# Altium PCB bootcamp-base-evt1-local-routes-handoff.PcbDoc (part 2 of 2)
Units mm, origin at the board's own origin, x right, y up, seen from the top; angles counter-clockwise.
Board outline 49.31 x 77.41 mm, 4 copper layers (Top Layer, Internal Plane 1, Internal Plane 2, Bottom Layer), stack 1.597 mm thick; 167 components, 119 nets, 1376 pads, 238 vias.
Unrouted connection lines stored in the file: 50.
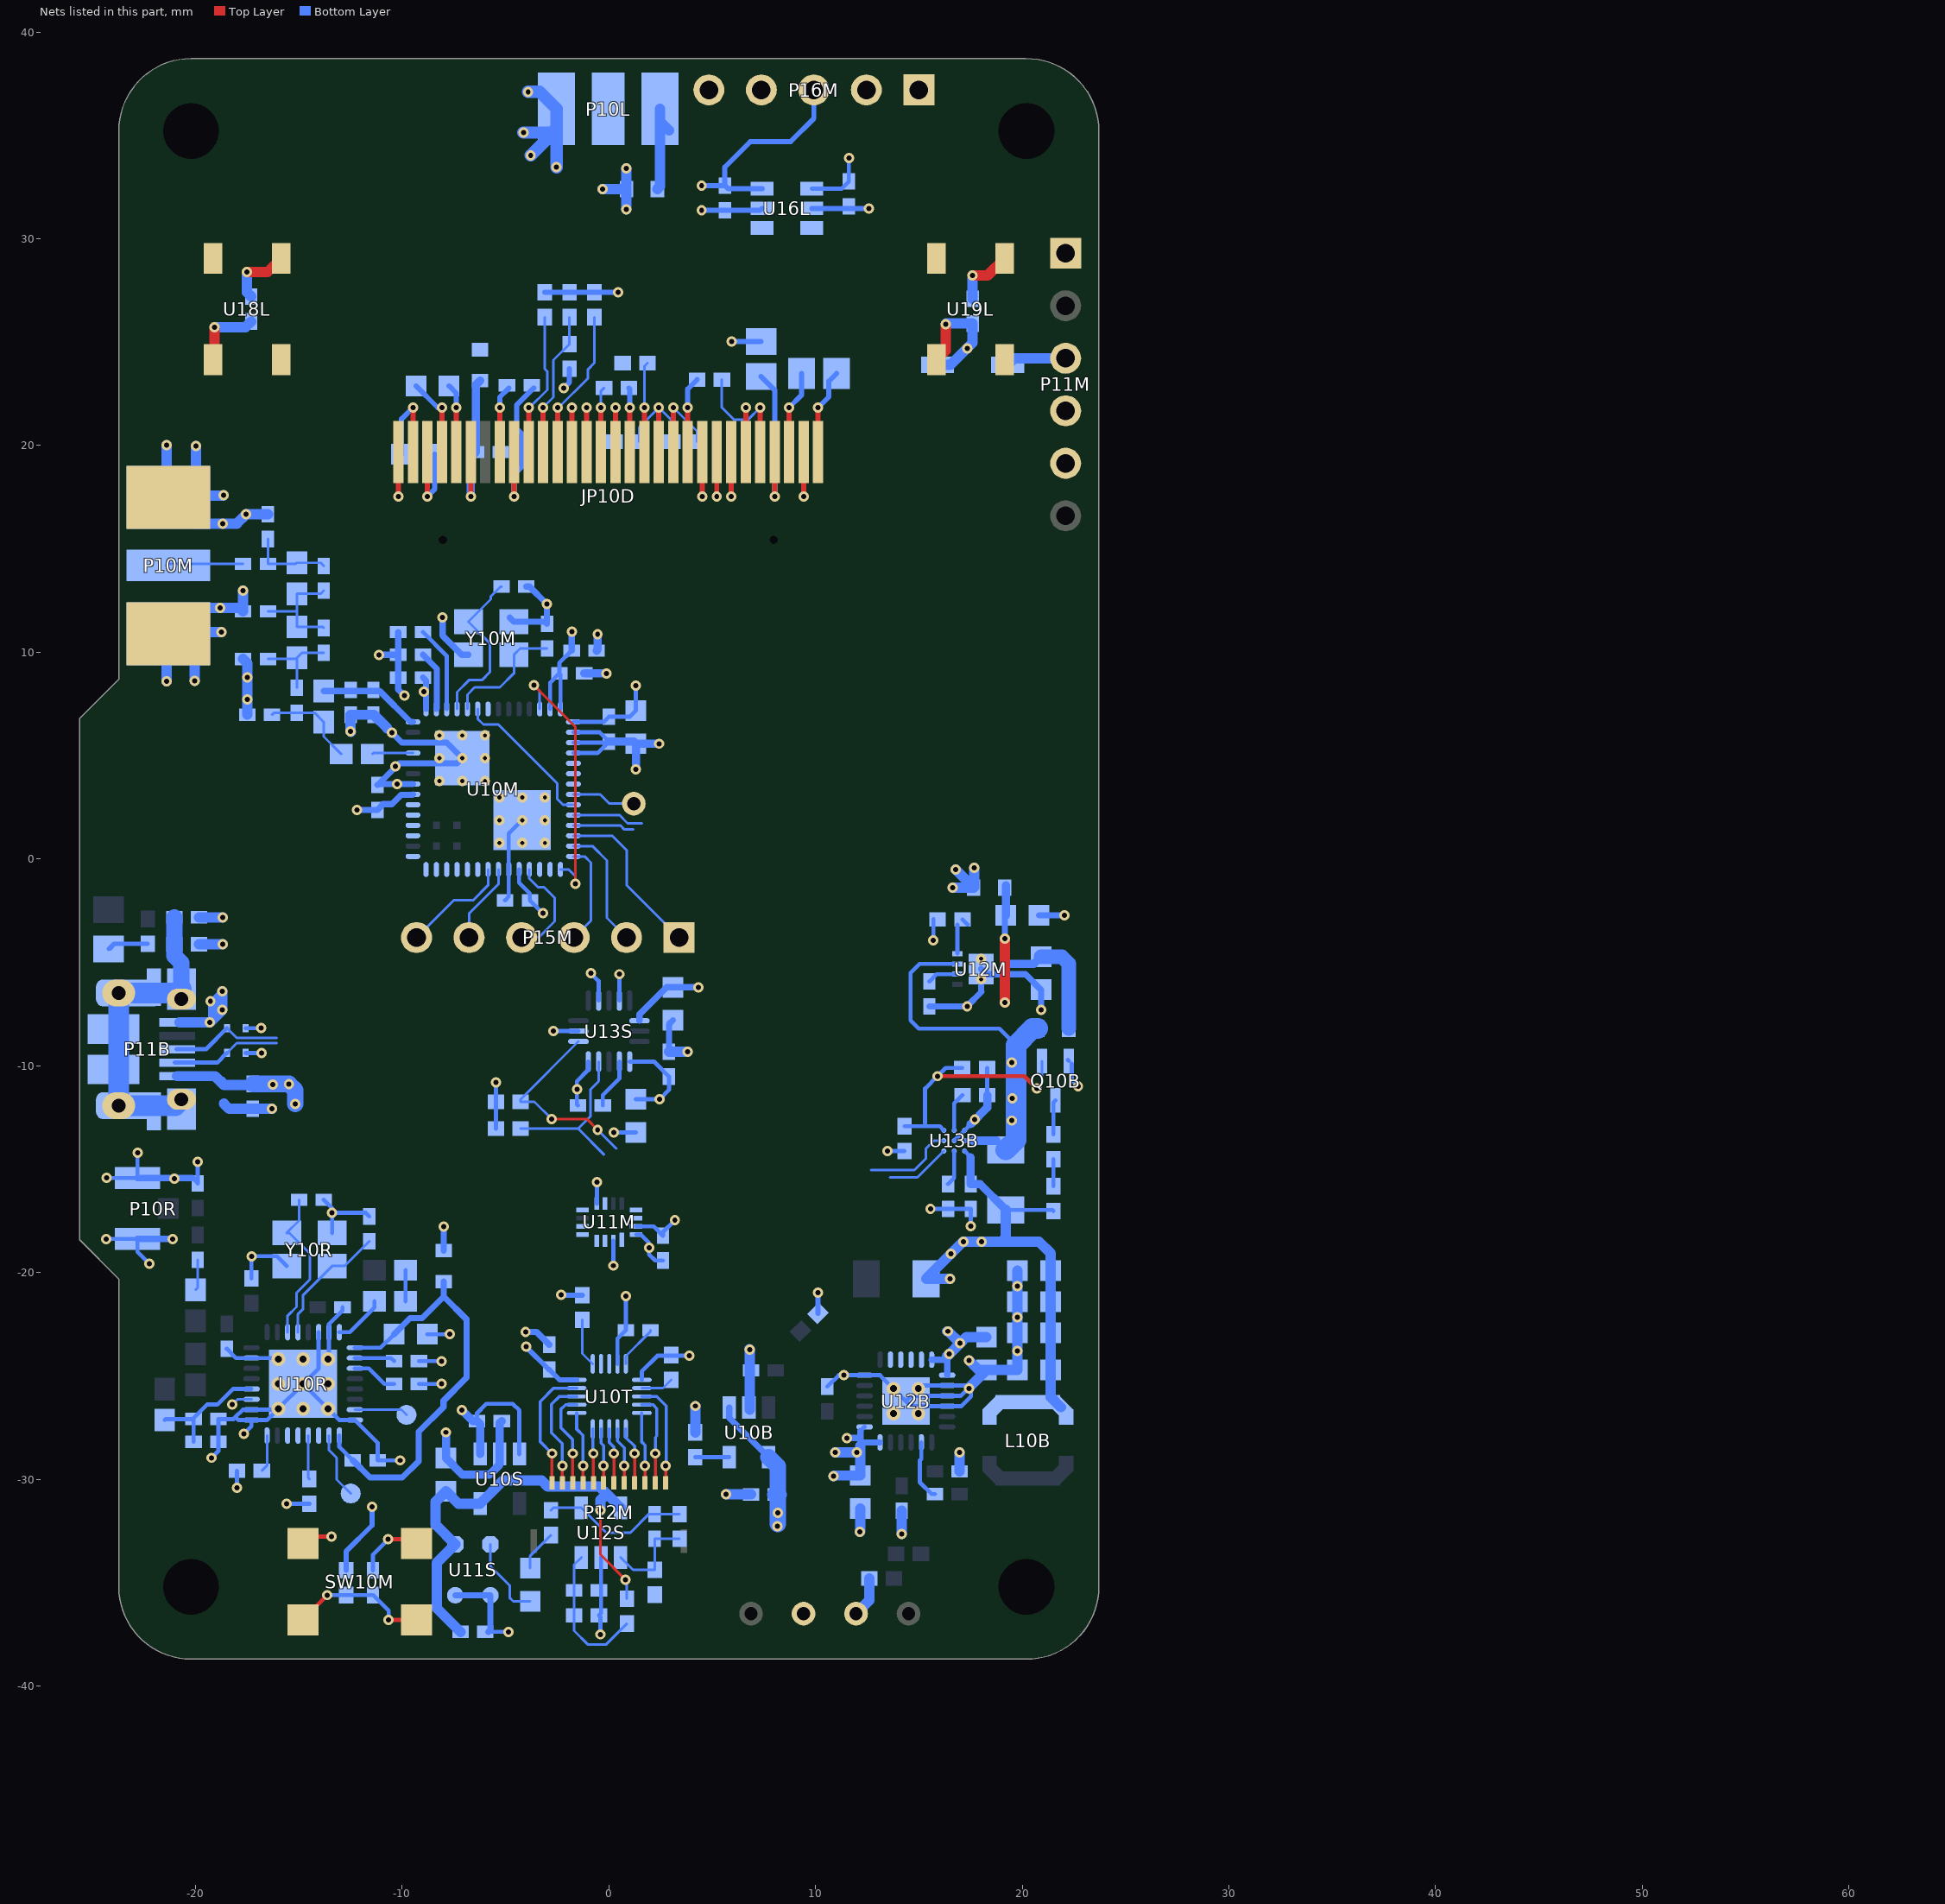
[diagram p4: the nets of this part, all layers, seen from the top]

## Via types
v1: diameter 0.5, hole 0.25, Top Layer to Bottom Layer, tented both sides, 205 vias
v2: diameter 0.5, hole 0.2, Top Layer to Bottom Layer, 18 vias
v3: diameter 0.66, hole 0.33, Top Layer to Bottom Layer, tented top, 13 vias
v4: diameter 0.5, hole 0.2, Top Layer to Bottom Layer, tented top, 2 vias

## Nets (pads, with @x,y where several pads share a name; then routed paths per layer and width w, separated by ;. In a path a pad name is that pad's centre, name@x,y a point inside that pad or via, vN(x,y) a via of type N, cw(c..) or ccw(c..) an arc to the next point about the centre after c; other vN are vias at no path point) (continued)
BLE_RDYN: R11R.1 U10M.26 U10R.16 | length 1.8
  Bottom Layer w0.125: R11R.1@-16.786,-29.584 -16.536,-29.334 U10R.16@-16.536,-27.884
BLE_REQN: R12R.1 U10M.7 U10R.12 | length 2.1
  Bottom Layer w0.125: U10R.12@-14.536,-27.884 -14.536,-29.934 R12R.1@-14.486,-29.984
BLE_RST: U10R.19 U11M.5 | length 1
  Bottom Layer w0.125: v1(-18.211,-26.384) -17.961,-26.134 U10R.19@-17.286,-26.134
BLE_VDDPA: C19R.2 C20R.2 L14R.2 U10R.20 | length 6
  Bottom Layer w0.2: L14R.2@-21.486,-27.134 -21.436,-27.084 C19R.2@-20.086,-27.084 ; C20R.2@-20.086,-28.184 C19R.2@-20.086,-27.084 ; U10R.20@-17.286,-25.634 -18.186,-25.634 -18.936,-26.384 -19.436,-26.384 -20.086,-27.034 C19R.2@-20.086,-27.084
BLE_XC1: C10R.1 U10R.28 Y10R.2 | length 6.2
  Bottom Layer w0.125: U10R.28@-15.036,-22.884 -15.036,-22.009 -14.786,-21.759 -14.786,-21.084 Y10R.2@-13.386,-19.684 -12.786,-19.684 C10R.1@-11.586,-18.484
BLE_XC2: C11R.1 U10R.27 Y10R.1 | length 7.6
  Bottom Layer w0.125: U10R.27@-15.536,-22.884 -15.536,-22.084 -15.111,-21.659 -15.111,-20.984 -14.461,-20.334 -14.461,-19.084 -15.461,-18.084 Y10R.1@-15.586,-18.084 -14.986,-17.484 C11R.1@-14.986,-16.484
BS0: JP10D.10 R11D.2 | length 7
  Top Layer w0.25: JP10D.10@-3.878,19.684 v1(-3.878,21.834)
  Bottom Layer w0.125: v1(-3.878,21.834) -3.838,21.834 -2.978,22.694 -2.978,23.584 -3.103,23.709 R11D.2@-3.103,26.209
BS1: JP10D.11 R15D.2 R16D.2 | length 7.1
  Top Layer w0.25: JP10D.11@-3.178,19.684 v1(-3.178,21.834)
  Bottom Layer w0.125: v1(-3.178,21.834) -2.678,22.334 -2.678,24.134 R16D.2@-1.903,24.909 R15D.2@-1.903,26.209
BS2: JP10D.12 R17D.2 | length 7.3
  Top Layer w0.25: JP10D.12@-2.478,19.684 v1(-2.478,21.834)
  Bottom Layer w0.125: v1(-2.478,21.834) -2.428,21.834 -1.003,23.259 -1.003,23.684 -0.703,23.984 R17D.2@-0.703,26.209
DAC0_OUT: J17M.1 U10M.8 | length 3.1
  Bottom Layer w0.125: U10M.8@-1.712,3.129 -0.417,3.129 0.033,2.679 J17M.1@1.208,2.679
DUART_RX: P11M.4 U10M.29
DUART_TX: P11M.5 U10M.31
GG_INT: Q10B.1 R22B.1 R28B.2 U11M.8 U13B.A1 | length 12.5
  Top Layer w0.2: v1(15.9,-10.5) 20.1,-10.5 v1(20.7,-11.1)
  Bottom Layer w0.125: v1(20.7,-11.1) 20.958,-10.842 Q10B.1@20.958,-9.771
  Bottom Layer w0.2: R22B.1@14.308,-12.921 15.3,-12.921 ; U13B.A1@16.208,-13.121 16.008,-12.921 15.3,-12.921 ; R28B.2@17.1,-10.1 16.3,-10.1 v1(15.9,-10.5) 15.3,-11.1 15.3,-12.921
GG_VDD: C26B.1 U13B.B3 | length 1.7
  Bottom Layer w0.2: C26B.1@16.408,-15.721 16.708,-15.421 U13B.B3@16.708,-14.121
GND: C10B.2 C10L.2 C10M.2 C10R.2 C10S.2 C10T.2 C11B.2 C11L.2 C11M.2 C11R.2 C11S.2 C11T.2 C12D.2 C12L.2 C12M.2 C12R.2 C13D.2 C13L.2 C13M.2 C13R.2 C14D.2 C14M.2 C14S.2 C15B.2 C15D.2 C15M.2 C15R.1 C15S.2 C16B.2 C16M.2 C16R.2 C16S.2 C17B.2 C17M.2 C17R.2 C17S.2 C18B.2 C18M.2 C18R.1 C18S.2 C19B.2 C19M.2 C19R.1 C19S.2 C20B.2 C20M.2 C20R.1 C21B.2 C21R.2 C22B.2 C23B.2 C24B.2 C25B.2 C25M.2 C26B.2 C26M.1 C27B.2 C27M.2 C28M.2 C29M.2 C30M.2 C31M.2 C32M.2 C33M.2 C34M.2 C35M.1 D11B.2 D12B.2 D13B.2 J12B.1 J13B.1 JP10D.1 JP10D.8 JP10D.16 JP10D.17 JP10D.21 JP10D.22 JP10D.23 JP10D.24 JP10D.25 JP10D.29 JP10D.30 P10L.1 P10M.2 P10R.GND P11B.5 P11M.1 P16M.4 Q10B.2 R10R.1 R11D.1 R13S.1 R14D.2 R15D.1 R16B.2 R17D.1 R18D.2 R20B.1 R23B.1 R24B.2 R28B.1 R34T.1 SW10M.1 SW10M.2 U10B.2 U10M.2 U10M.3 U10M.4 U10M.20 U10M.36 U10M.38 U10M.40 U10M.61 U10M.62 U10R.8 U10R.17 U10R.18 U10R.23 U10R.30 U10R.31 U10R.33 U10S.2 U10T.4 U10T.6 U11M.9 U11M.16 U11S.2 U11S.3 U12B.12 U12B.20 U12B.21 U12B.22 U12B.25 U12M.3 U12M.9 U12S.2 U13B.B2 U13B.C1 U13S.5 U13S.7 U13S.10 U13S.12 U16L.2 U16L.5 U18L.3 U19L.3 Y10M.3 Y10M.4 Y10R.3 Y10R.4 | length 274.2
  Top Layer w0.2: SW10M.2@-14.8,-33.1 -14.475,-32.775 v1(-13.425,-32.775) ; v1(-10.675,-32.9) -9.5,-32.9 SW10M.1@-9.3,-33.1
  Top Layer w0.25: v1(-10.178,17.534) JP10D.1@-10.178,19.684 ; JP10D.8@-5.278,19.684 v1(-5.278,21.834) ; JP10D.16@0.322,19.684 v1(0.322,21.834) ; JP10D.17@1.022,19.684 v1(1.022,21.834) ; JP10D.21@3.822,19.684 v1(3.822,21.834) ; v1(4.522,17.534) JP10D.22@4.522,19.684 ; v1(5.222,17.534) JP10D.23@5.222,19.684 ; v1(5.922,17.534) JP10D.24@5.922,19.684 ; JP10D.25@6.622,19.684 v1(6.622,21.834) ; v1(9.422,17.534) JP10D.29@9.422,19.684 ; JP10D.30@10.122,19.684 v1(10.122,21.834)
  Top Layer w0.5: v1(-17.5,28.4) -16.5,28.4 U18L.3@-15.85,29.05 ; v1(17.6,28.225) 18.325,28.225 U19L.3@19.15,29.05
  Bottom Layer w0.2: v1(-24.325,-18.375) P10R.GND@-22.8,-18.375 -22.8,-19 v1(-22.225,-19.575) ; v1(-24.3,-15.425) P10R.GND@-22.8,-15.425 v1(-22.8,-14.2) ; v1(-21.1,-18.375) v1@-21.075,-18.4 ; C15R.1@-20.145,-15.425 C15R.1@-19.886,-15.684 v1(-19.886,-14.636) v1@-19.875,-14.625 ; v1(-19.211,-28.959) -18.886,-28.634 C20R.1@-18.886,-28.184 C19R.1@-18.886,-27.084 -18.161,-27.084 -18.061,-26.984 ; C13R.2@-18.486,-23.684 -18.036,-24.134 U10R.23@-17.286,-24.134 -16.036,-24.134 v3(-15.986,-24.184) ; v1(-17.661,-27.809) -17.286,-27.434 U10R.17@-17.286,-27.134 ; D12B.2@-17.573,-9.379 v1(-16.798,-9.379) ; D13B.2@-17.573,-8.179 v1(-16.823,-8.179) ; R10R.1@-17.286,-20.284 v1(-17.286,-19.209) -16.061,-19.209 Y10R.4@-15.586,-19.684 ; U10R.30@-14.036,-22.884 -14.036,-24.634 v3(-14.786,-25.384) ; C11R.2@-13.786,-16.484 -13.386,-16.884 v1(-13.386,-17.109) ; v3(-13.586,-24.184) -13.536,-24.134 U10R.31@-13.536,-22.884 -13.536,-22.484 -12.886,-21.834 C12R.2@-12.886,-21.684 ; Y10R.3@-13.386,-18.084 v1(-13.386,-17.109) ; C10R.2@-11.586,-17.284 -11.761,-17.109 v1(-13.386,-17.109) ; C31M.2@-11.408,-34.4 -11.408,-33.633 v1(-10.675,-32.9) ; v1(-10.086,-29.084) C21R.2@-11.186,-29.084 -11.186,-28.234 U10R.8@-12.286,-27.134 -13.036,-27.134 v3(-13.586,-26.584) v3(-14.786,-25.384) ; C18R.1@-9.186,-25.384 v1(-8.086,-25.384) ; C17R.2@-9.186,-24.284 v1(-8.086,-24.284) ; C16R.2@-8.786,-22.984 v1(-7.686,-22.984) ; C14S.2@-5.823,-37.379 v1(-4.848,-37.379) ; C30M.2@-5.017,-1.996 -4.842,-1.821 U10M.20@-4.842,-0.501 -4.842,1.229 v2(-4.192,1.879) ; v1(-2.692,-8.321) U13S.7@-1.467,-8.321 ; U10M.4@-1.712,5.129 -0.542,5.129 C12M.2@-0.042,5.629 ; U10M.3@-1.712,5.629 C12M.2@-0.042,5.629 ; U10M.2@-1.712,6.129 -0.442,6.129 C12M.2@0.008,5.679 C12M.2@-0.042,5.629 ; C19S.2@-1.492,-11.921 -1.542,-11.871 -1.542,-10.746 -0.992,-10.196 U13S.5@-0.992,-9.796 ; v1@-0.892,-5.496 -0.492,-5.896 U13S.10@-0.492,-6.846 ; U11M.9@-0.579,-16.667 v1(-0.579,-15.617) ; v1(-0.4,-37.5) -0.4,-36.656 R13S.1@-0.479,-36.577 -0.379,-36.477 -0.379,-35.377 U12S.2@-0.379,-33.777 ; v1(0.233,-13.221) C16S.2@1.308,-13.221 ; U10T.4@0.422,-24.416 0.422,-23.191 C11T.2@0.822,-22.791 v1(0.822,-21.141) ; U13S.12@0.508,-6.846 v1(0.508,-5.571) ; U11M.16@1.321,-18.167 1.546,-18.167 1.946,-18.567 1.946,-19.117 2.246,-19.417 C32M.2@2.621,-19.417 ; U10T.6@1.597,-25.191 1.597,-24.778 2.35,-24.025 v1@3.75,-24.025 ; C21B.2@10.572,-25.516 11.122,-24.966 U12B.12@12.372,-24.966 13.122,-24.966 v3(13.772,-25.616) U12B.25@14.372,-26.216 ; v3(14.972,-25.616) 15.122,-25.466 U12B.20@16.372,-25.466 v1@17.522,-25.466 ; v1(15.558,-16.921) C25B.2@17.508,-16.921 v1(17.508,-17.746) ; U13B.B2@16.708,-13.621 U13B.C1@17.208,-13.121 17.508,-12.821 ; R28B.1@18.3,-10.1 18.3,-11.413 R23B.1@18.308,-11.421 ; Q10B.2@22.208,-9.721 Q10B.2@22.258,-9.771 ; Q10B.2@22.4,-9.9 22.4,-10.7 v1(22.7,-11) ; -18.061,-26.984 -17.911,-27.134 U10R.17@-17.286,-27.134 ; -18.061,-26.984 -17.711,-26.634 U10R.18@-17.286,-26.634 U10R.33@-16.036,-26.634 ; U10R.17@-17.286,-27.134 -16.536,-27.134 U10R.33@-16.036,-26.634 ; U10R.33@-16.036,-26.634 v3(-15.986,-26.584) v3(-14.786,-25.384) ; U12B.25@14.372,-26.216 14.622,-26.466 U12B.22@16.372,-26.466 17.047,-26.466 17.522,-25.991 v1@17.522,-25.466 ; U12B.25@14.372,-26.216 14.622,-25.966 U12B.21@16.372,-25.966 17.022,-25.966 v1@17.522,-25.466
  Bottom Layer w0.25: C12D.2@-5.228,19.684 -5.278,19.734 v1(-5.278,21.834) -5.278,22.334 C13D.2@-4.828,22.784 ; R11D.1@-3.103,27.409 R15D.1@-1.903,27.409 R17D.1@-0.703,27.409 v1(0.447,27.409) ; R14D.2@0.972,22.784 1.022,22.734 v1(1.022,21.834) ; v1(3.822,21.834) 3.822,22.734 R18D.2@4.272,23.184 ; v1(4.491,31.372) C11L.2@5.616,31.372 7.316,31.372 U16L.5@7.416,31.472 ; v1(5.947,25.034) C14D.2@7.372,25.034 ; U16L.2@9.816,31.472 v1(12.591,31.472) ; v1(10.122,21.834) 10.647,22.359 10.647,23.109 C15D.2@11.022,23.484
  Bottom Layer w0.3: P10R.GND@-22.8,-18.375 v1(-21.1,-18.375) ; P10R.GND@-22.8,-15.425 C15R.1@-20.145,-15.425 ; C16M.2@-11.192,3.579 C16M.2@-11.142,3.629 ; v1(-11.117,9.879) C17M.2@-10.192,9.879 ; -10.717,6.329 -10.017,5.629 U10M.40@-9.472,5.629 -7.842,5.629 v2(-7.092,4.879) -7.342,4.629 U10M.38@-9.472,4.629 -10.142,4.629 C16M.2@-11.142,3.629 ; C18M.2@-10.192,10.979 C17M.2@-10.192,9.879 ; v1(-9.892,7.904) -10.192,8.204 C17M.2@-10.192,9.879 ; U10M.36@-9.472,3.629 C16M.2@-11.142,3.629 ; v1(-8.042,11.679) -8.042,10.804 -7.117,9.879 Y10M.4@-6.792,9.879 ; U11S.2@-7.429,-35.607 U11S.3@-5.729,-35.607 -5.729,-37.285 C14S.2@-5.823,-37.379 ; Y10M.3@-4.792,11.679 Y10M.3@-4.592,11.479 -3.092,11.479 C14M.2@-2.992,11.379 v1(-2.992,12.329) -3.842,13.179 C15M.2@-3.992,13.179 ; v1(-4.028,-22.866) -3.503,-22.866 C10T.2@-2.878,-23.491 ; C17S.2@2.908,-9.321 2.908,-7.992 C18S.2@3.1,-7.8 ; C35M.1@15.508,-7.121 v1(17.333,-7.121) 18.033,-6.421 18.008,-6.396 v4(18.008,-5.821) ; U12M.9@18.008,-5.321 18.258,-5.571 U12M.3@19.158,-5.571 20.158,-5.571 C33M.2@20.908,-6.321 v1(20.908,-7.296) ; C34M.2@20.808,-2.721 v1(22.033,-2.721)
  Bottom Layer w0.4: v1(-7.879,-27.727) C11S.2@-7.879,-28.977 -7.079,-29.777 -5.779,-29.777 -5.279,-29.277 U10S.2@-5.279,-28.777 -5.279,-27.277 C10S.2@-5.179,-27.177 ; C10M.2@-1.192,8.979 v1(-0.117,8.979) ; C13M.2@-0.592,10.079 -0.542,10.129 v1(-0.542,10.879) ; C12M.2@0.008,5.679 1.208,5.679 C11M.2@1.308,5.579 ; v1(1.308,4.329) C11M.2@1.308,5.579 ; v1(2.433,5.579) C11M.2@1.308,5.579 ; 17.508,-12.821 18.308,-12.021 R23B.1@18.308,-11.421
  Bottom Layer w0.5: v1(-21.392,8.604) -21.392,10.977 P10M.2@-21.228,10.977 ; v1(-21.392,20.029) -21.392,17.581 P10M.2@-21.228,17.581 ; P11B.5@-20.769,-7.907 -19.301,-7.907 v1(-19.298,-7.904) v1(-18.698,-7.304) v1@-18.698,-6.526 ; v1(-20.025,8.625) -20.025,9.616 P10M.2@-21.307,10.898 P10M.2@-21.228,10.977 ; v1(-19.975,19.975) -19.975,18.834 P10M.2@-21.228,17.581 ; R24B.2@-19.821,-4.123 v1(-18.671,-4.123) ; C27B.2@-19.821,-2.823 v1(-18.671,-2.823) ; v1@-19.148,-7.754 -19.148,-6.976 v1@-18.698,-6.526 ; v1(-18.742,10.979) v1(-18.742,10.979) P10M.2@-21.228,10.977 ; v1(-18.698,-6.404) v1@-18.698,-6.526 ; v1(-18.642,17.604) -18.665,17.581 P10M.2@-21.228,17.581 ; D11B.2@-18.623,-11.829 -18.373,-12.079 C24B.2@-17.223,-12.079 v1(-16.298,-12.079) ; C26M.1@-17.692,9.679 -17.492,9.479 C25M.2@-17.492,6.979 ; v1(-17.692,12.979) C27M.2@-17.692,11.979 -17.863,12.15 v1(-18.8,12.15) -20.055,12.15 P10M.2@-21.228,10.977 ; v1(-17.5,28.4) -17.5,27.4 C12L.2@-17.3,27.2 ; C28M.2@-16.492,16.679 v1(-17.542,16.679) -17.995,16.225 v1(-18.675,16.225) -20.03,16.225 P10M.2@-21.307,17.502 P10M.2@-21.228,17.581 ; v1@-12.467,6.154 v1(-12.492,6.179) C20M.2@-12.492,6.979 C19M.2@-11.392,6.979 -11.367,6.979 -10.717,6.329 ; C17S.2@2.908,-9.321 v1(3.808,-9.321) ; R16B.2@4.178,-27.728 v1(4.178,-26.453) ; v1(5.678,-30.728) C11B.2@6.878,-30.728 ; v1@6.791,-23.703 v1(6.816,-23.728) U10B.2@6.816,-26.628 ; J13B.1@11.96,-36.5 12.6,-35.86 R20B.1@12.6,-34.8 ; v1(12.15,-32.55) 12.172,-32.528 C16B.2@12.172,-31.416 ; v1(14.172,-32.641) C23B.2@14.172,-31.516 ; C22B.2@16.972,-29.616 v1(16.972,-28.691) ; v1(17.422,-24.241) 17.897,-24.716 C20B.2@18.272,-24.716 ; v1@17.522,-25.466 C20B.2@18.272,-24.716 ; C13L.2@17.6,27.1 v1(17.6,28.225) ; C17B.2@19.772,-19.916 C19B.2@19.772,-21.416 C18B.2@19.772,-22.916 v1(19.772,-23.791) C15B.2@19.772,-24.716 C20B.2@18.272,-24.716
  Bottom Layer w0.6: v1(-4.128,35.134) -2.853,35.134 -2.803,35.084 P10L.1@-2.528,35.359 ; v1(-3.903,37.109) -3.353,37.109 P10L.1@-2.528,36.284 P10L.1@-2.528,35.359 ; v1(-3.778,34.034) P10L.1@-2.528,35.284 ; v1(-2.528,33.459) P10L.1@-2.528,35.284 ; P10L.1@-2.528,35.284 P10L.1@-2.528,35.359
  other v1: 17.422,-25.616 11.372,-24.966 3.9,-24.025 19.772,-22.166 19.772,-20.666 1.946,-18.792 -21.025,-15.45 17.708,-12.596 -1.542,-11.146 -19.273,-6.879 -0.867,-5.521 -10.242,3.629 -10.317,4.479 -10.492,6.104 -17.492,7.729 -17.492,8.779
  other v2: -5.292,0.779 -4.192,0.779 -3.092,0.779 -5.292,1.879 -3.092,1.879 -5.292,2.979 -4.192,2.979 -3.092,2.979 -8.192,3.779 -7.092,3.779 -5.992,3.779 -8.192,4.879 -5.992,4.879 -8.192,5.979 -7.092,5.979 -5.992,5.979
  other v3: 13.772,-26.816 14.972,-26.816 -14.786,-26.584 -15.986,-25.384 -13.586,-25.384 -14.786,-24.184
  other v4: 18.008,-4.821
GPIO_INT: U10M.17 U11M.1
LDO_CC: C35M.2 U12M.6 | length 1.5
  Bottom Layer w0.2: C35M.2@15.508,-5.921 15.858,-5.571 U12M.6@16.858,-5.571
LED0: U10M.6 U16L.4
LED0_HV: U16L.3 U19L.4
LED1: U18L.4 U19L.2
LED2: P10L.2 U18L.2
MCU_RESET: C31M.1 P16M.5 R12M.2 SW10M.3 SW10M.4 U10M.33 U11M.10 | length 6.8
  Top Layer w0.2: SW10M.4@-14.8,-36.8 -13.625,-35.625 v1(-13.625,-35.6) ; v1(-10.65,-36.8) SW10M.3@-9.3,-36.8
  Bottom Layer w0.2: v1(-13.625,-35.6) R12M.2@-12.708,-35.6 C31M.1@-11.408,-35.6 -10.65,-36.358 v1(-10.65,-36.8)
MIC_OUT: R10S.1 R26B.1 R27B.2 U10M.5 | length 1.3
  Bottom Layer w0.2: R26B.1@21.508,-15.821 R27B.2@21.508,-14.521
MPR_IRQ: R26T.1 U10T.1 U11M.3 | length 2.3
  Bottom Layer w0.125: R26T.1@-1.278,-22.291 -1.278,-23.916 U10T.1@-0.778,-24.416
NetC11T_1: C11T.1 U10T.5 | length 2.1
  Bottom Layer w0.125: U10T.5@0.822,-24.416 0.822,-24.041 2.022,-22.841 C11T.1@2.022,-22.791
NetC12S_1: C12S.1 R10S.2 R11S.2 U12S.1 | length 4.6
  Bottom Layer w0.125: U12S.1@0.571,-33.777 1.171,-34.377 R10S.2@2.221,-34.377 C12S.1@2.221,-32.877 R11S.2@3.421,-32.877
NetC12S_2: C12S.2 R11S.1 R14S.1 U12S.4 | length 7.1
  Bottom Layer w0.125: R14S.1@-2.8,-31.5 -2.677,-31.377 U12S.4@-1.329,-31.377 -0.129,-32.577 1.046,-32.577 1.946,-31.677 C12S.2@2.221,-31.677 R11S.1@3.421,-31.677
NetC13S_1: C13S.1 U11S.4 | length 4
  Bottom Layer w0.125: U11S.4@-5.729,-33.147 -5.729,-34.196 -4.8,-35.125 -4.8,-35.725 -4.625,-35.9 C13S.1@-3.8,-35.9
NetC13S_2: C13S.2 R14S.2 | length 2
  Bottom Layer w0.125: C13S.2@-3.8,-34.3 -3.8,-33.7 R14S.2@-2.8,-32.7
NetC14B_1: C14B.1 U12B.2 | length 2.9
  Bottom Layer w0.2: U12B.2@15.122,-28.216 15.122,-29.016 15.047,-29.091 15.047,-30.141 15.622,-30.716 C14B.1@15.772,-30.716
NetC14R_1: C14R.1 L12R.2 | length 1.5
  Bottom Layer w0.125: L12R.2@-19.986,-20.834 -19.886,-20.734 C14R.1@-19.886,-19.384
NetC15S_1: C15S.1 R12S.1 R13S.2 U12S.3 | length 6.9
  Bottom Layer w0.125: U12S.3@-1.329,-33.777 -1.679,-34.127 R13S.2@-1.679,-36.577 -1.679,-37.321 -1,-38 -0.144,-38 R12S.1@0.877,-36.979
NetC17M_1: C17M.1 U10M.44 | length 2.9
  Bottom Layer w0.3: C17M.1@-8.992,9.879 -8.317,9.204 -8.317,7.284 U10M.44@-8.342,7.259
NetC17R_1: C17R.1 U10R.2 | length 2
  Bottom Layer w0.2: U10R.2@-12.286,-24.134 -10.536,-24.134 C17R.1@-10.386,-24.284
NetC18M_1: C18M.1 U10M.45 | length 4.2
  Bottom Layer w0.2: C18M.1@-8.992,10.979 -7.842,9.829 U10M.45@-7.842,7.259
NetC18R_2: C18R.2 U10R.3 | length 2.2
  Bottom Layer w0.2: U10R.3@-12.286,-24.634 -11.611,-24.634 -10.861,-25.384 C18R.2@-10.386,-25.384
NetC19S_1: C19S.1 U13S.2 | length 2.5
  Bottom Layer w0.2: C19S.1@-0.292,-11.921 -0.292,-11.421 0.508,-10.621 U13S.2@0.508,-9.796
NetC21M_1: C21M.1 C23M.2 C26M.2 L12M.1 | length 4.3
  Bottom Layer w0.125: C26M.2@-16.492,9.679 -15.142,9.679 L12M.1@-15.092,9.729 ; C23M.2@-15.092,8.279 L12M.1@-15.092,9.729 ; C21M.1@-13.792,9.979 -14.842,9.979 L12M.1@-15.092,9.729
NetC21M_2: C21M.2 C22M.1 C27M.1 L12M.2 L13M.1 | length 5.7
  Bottom Layer w0.125: C27M.1@-16.492,11.979 -15.142,11.979 -15.092,12.029 ; C21M.2@-13.792,11.179 -13.842,11.229 L12M.2@-15.092,11.229 -15.092,12.029 ; C22M.1@-13.792,12.979 -13.942,12.829 L13M.1@-15.092,12.829 -15.092,12.029
NetC22M_2: C22M.2 C24M.1 C28M.1 L13M.2 | length 4
  Bottom Layer w0.125: C28M.1@-16.492,15.479 C24M.1@-16.492,14.279 -15.142,14.279 L13M.2@-15.092,14.329 -13.942,14.329 C22M.2@-13.792,14.179
NetC23M_1: C23M.1 C25M.1 L10M.2 L11M.2 | length 4.6
  Bottom Layer w0.125: C25M.1@-16.292,6.979 -16.192,7.079 C23M.1@-15.092,7.079 -14.242,7.079 L10M.2@-13.792,6.629 -13.792,5.929 L11M.2@-12.942,5.079
NetC24M_2: C24M.2 P10M.1 | length 3.7
  Bottom Layer w0.125: P10M.1@-21.407,14.2 -21.328,14.279 C24M.2@-17.692,14.279
NetC27B_1: C27B.1 P11B.0 R24B.1 | length 15.8
  Bottom Layer w0.8: C27B.1@-21.021,-2.823 R24B.1@-21.021,-4.123 -21.021,-4.679 -20.677,-5.023 P11B.0@-20.677,-6.775
  Bottom Layer w1: P11B.0@-20.677,-11.625 -20.977,-11.925 P11B.0@-23.707,-11.925 P11B.0@-23.707,-6.475 P11B.0@-23.232,-6.475 -20.852,-6.475 P11B.0@-20.677,-6.3
NetD10B_1: D10B.1 R17B.2 | length 2.2
  Bottom Layer w0.2: D10B.1@-24.2,-4.35 -23.95,-4.1 R17B.2@-22.3,-4.1 ; D10B.1@-24.123,-4.329 D10B.1@-23.973,-4.179
NetD10M_1: D10M.1 P11M.3 | length 2.9
  Bottom Layer w0.5: D10M.1@19.3,23.9 19.62,24.22 P11M.3@22.1,24.22
NetJ10R_1: J10R.1 U10R.7 | length 2.6
  Bottom Layer w0.125: U10R.7@-12.286,-26.634 -10.036,-26.634 J10R.1@-9.786,-26.884
NetJ11R_1: J11R.1 U10R.10 | length 3.2
  Bottom Layer w0.125: U10R.10@-13.536,-27.884 -13.536,-28.584 -13.161,-28.959 -13.161,-30.009 J11R.1@-12.486,-30.684
NetJP10D_20: JP10D.20 R13D.1 | length 4.3
  Top Layer w0.25: JP10D.20@3.122,19.684 v1(3.122,21.834)
  Bottom Layer w0.125: v1(3.122,21.834) 4.272,20.684 R13D.1@4.272,20.184
NetL10R_1: L10R.1 L11R.2 | length 1.5
  Bottom Layer w0.2: L11R.2@-9.836,-21.384 L10R.1@-9.836,-19.884
NetL11R_1: L11R.1 U10R.32 | length 2.5
  Bottom Layer w0.2: U10R.32@-13.036,-22.884 -12.536,-22.884 -11.336,-21.684 L11R.1@-11.336,-21.384
NetQ10B_3: Q10B.3 R27B.1 | length 1.7
  Bottom Layer w0.2: R27B.1@21.508,-13.321 21.508,-11.771 Q10B.3@21.608,-11.671
NetR13M_2: R13M.2 U12M.8 | length 1.8
  Bottom Layer w0.2: U12M.8@16.858,-4.571 R13M.2@16.858,-3.171 ; R13M.2@17.108,-2.921 R13M.2@17.358,-3.171
NetR16B_1: R16B.1 U10B.5 | length 1.6
  Bottom Layer w0.2: R16B.1@4.178,-28.928 U10B.5@5.828,-28.928
NetR23B_2: R23B.2 U13B.B1 | length 1.9
  Bottom Layer w0.2: U13B.B1@16.708,-13.121 16.708,-11.821 R23B.2@17.108,-11.421
NetR34T_2: R34T.2 U10T.7 | length 1.6
  Bottom Layer w0.125: U10T.7@1.597,-25.591 2.622,-25.591 R34T.2@3.022,-25.191
OLED_C1N: C11D.1 JP10D.5 | length 3.3
  Top Layer w0.25: JP10D.5@-7.378,19.684 v1(-7.378,21.834)
  Bottom Layer w0.25: C11D.1@-7.728,22.884 -7.378,22.534 v1(-7.378,21.834)
OLED_C1P: C11D.2 JP10D.4 | length 3.8
  Top Layer w0.25: JP10D.4@-8.078,19.684 v1(-8.078,21.834)
  Bottom Layer w0.25: C11D.2@-9.328,22.884 -8.278,21.834 v1(-8.078,21.834)
OLED_C2N: C10D.1 JP10D.3 | length 4.3
  Top Layer w0.25: v1(-8.778,17.534) JP10D.3@-8.778,19.684
  Bottom Layer w0.25: v1(-8.778,17.534) -8.428,17.884 C10D.1@-8.428,19.584
OLED_C2P: C10D.2 JP10D.2 | length 4.6
  Top Layer w0.25: JP10D.2@-9.478,19.684 v1(-9.478,21.834)
  Bottom Layer w0.25: C10D.2@-10.028,19.584 -10.028,21.284 v1(-9.478,21.834)
OLED_CS: JP10D.13 U10M.16 | length 2.1
  Top Layer w0.25: JP10D.13@-1.778,19.684 v1(-1.778,21.834)
OLED_DC: JP10D.15 R14D.1 U10M.27 | length 3.2
  Top Layer w0.25: JP10D.15@-0.378,19.684 v1(-0.378,21.834)
  Bottom Layer w0.125: v1(-0.378,21.834) -0.378,22.634 R14D.1@-0.228,22.784
OLED_IREF: JP10D.26 R18D.1 | length 5.8
  Top Layer w0.25: JP10D.26@7.322,19.684 v1(7.322,21.834)
  Bottom Layer w0.125: R18D.1@5.472,23.184 5.472,21.834 6.047,21.259 6.747,21.259 v1(7.322,21.834)
OLED_RES: JP10D.14 U11M.4 | length 2.1
  Top Layer w0.25: JP10D.14@-1.078,19.684 v1(-1.078,21.834)
OLED_VCC: C15D.1 JP10D.28 | length 4
  Top Layer w0.25: JP10D.28@8.722,19.684 v1(8.722,21.834)
  Bottom Layer w0.25: v1(8.722,21.834) 9.322,22.434 C15D.1@9.322,23.484
OLED_VCOMH: C14D.1 JP10D.27 | length 8.2
  Top Layer w0.25: v1(8.022,17.534) JP10D.27@8.022,19.684
  Bottom Layer w0.25: C14D.1@7.372,23.334 8.022,22.684 v1(8.022,17.534)
P3.0V: C10M.1 C10T.1 C11L.1 C11M.1 C12M.1 C13D.1 C13M.1 C16M.1 C16R.1 C16S.1 C17S.1 C18S.1 C21R.1 C29M.1 C30M.1 C32M.1 C34M.1 J12R.1 J16M.1 JP10D.9 P16M.3 R10M.2 R11M.2 R11R.2 R12M.1 R12R.2 R13M.1 R16D.1 R19B.2 R22B.2 R26T.2 U10M.1 U10M.19 U10M.35 U10M.43 U10M.55 U10M.56 U10R.1 U10R.9 U10T.20 U11M.2 U11M.15 U12M.1 U12M.4 U13S.1 U13S.14 U16L.6 | length 96.4
  Top Layer w0.25: v1(-4.578,17.534) JP10D.9@-4.578,19.684
  Top Layer w0.5: v1(19.158,-6.946) v1(19.158,-3.846)
  Bottom Layer w0.2: v1(-17.986,-30.409) R11R.2@-17.986,-29.584 ; v1(-15.586,-31.184) R12R.2@-14.486,-31.184 ; U10R.9@-13.036,-27.884 -13.036,-28.434 C21R.1@-12.386,-29.084 ; U10R.1@-12.286,-23.634 -11.036,-23.634 C16R.1@-10.386,-22.984 ; v1(-5.467,-10.796) -5.463,-10.8 R10M.2@-5.463,-13.041 ; U10M.19@-4.342,-0.501 -4.342,-1.146 -3.817,-1.671 C30M.1@-3.817,-1.996 v1(-3.192,-2.621) v1@-3.142,-2.621 ; U10M.55@-2.842,7.259 -2.842,8.529 C10M.1@-2.392,8.979 ; U10M.56@-2.342,7.259 -2.342,8.929 C10M.1@-2.392,8.979 ; v1@-1.8,11 v1(-1.792,10.992) ; C13M.1@-1.792,10.079 -2.392,9.479 C10M.1@-2.392,8.979 ; U10M.1@-1.712,6.629 -0.242,6.629 C12M.1@0.008,6.879 1.008,6.879 C11M.1@1.308,7.179 v1(1.308,8.379) ; v1(0.221,-19.667) U11M.2@0.221,-18.467 ; U13S.1@1.008,-9.796 2.183,-9.796 C17S.1@2.908,-10.521 2.908,-11.171 v1(2.458,-11.621) C16S.1@1.308,-11.621 ; U11M.15@1.321,-17.767 2.171,-17.767 C32M.1@2.621,-18.217 2.621,-18.042 v1(3.196,-17.467) ; v1(13.483,-14.121) R22B.2@14.308,-14.121 ; v1(15.7,-3.925) R13M.1@15.7,-2.9 ; v1(19.158,-6.946) U12M.4@19.158,-6.071 ; C34M.1@19.158,-2.771 C34M.1@19.208,-2.721
  Bottom Layer w0.25: R12M.1@-12.708,-34.4 -12.708,-33.483 -11.45,-32.225 v1(-11.45,-31.325) ; v1(-4.578,17.534) -4.578,18.609 -4.203,18.984 -4.203,20.559 -4.453,20.809 -4.453,21.967 -3.636,22.784 C13D.1@-3.628,22.784 ; v1(-4.003,-23.591) -2.903,-24.691 C10T.1@-2.878,-24.691 -2.378,-25.191 U10T.20@-1.553,-25.191 ; v1@-2.3,-21.091 R26T.2@-1.278,-21.091 ; v1(-2.178,22.784) -1.903,23.059 R16D.1@-1.903,23.709 ; v1(4.491,32.572) C11L.1@5.616,32.572 ; U16L.6@7.416,32.422 5.766,32.422 C11L.1@5.616,32.572 ; P16M.3@9.92,37.2 9.92,35.82 8.8,34.7 6.85,34.7 5.616,33.466 C11L.1@5.616,32.572 ; R19B.2@10.124,-21.976 v1(10.125,-20.975)
  Bottom Layer w0.3: C21R.1@-12.386,-29.084 -11.561,-29.909 -9.986,-29.909 -9.2,-29.124 -9.2,-27.7 -8,-26.5 -8,-26.2 -6.886,-25.086 -6.886,-22.259 -7.986,-21.159 ; v1(-12.175,2.375) -12.171,2.379 C16M.1@-11.192,2.379 -10.917,2.654 -10.492,2.654 -10.042,3.104 -9.497,3.104 U10M.35@-9.472,3.129 ; C16R.1@-10.386,-22.984 -9.611,-22.209 -9.036,-22.209 -7.986,-21.159 ; C29M.1@-8.992,8.779 -8.842,8.629 U10M.43@-8.842,7.259 ; J12R.1@-7.986,-20.434 -7.986,-21.159 ; J12R.1@-7.986,-18.934 v1(-7.986,-17.784) ; C13M.1@-1.792,10.079 v1(-1.792,10.992) ; U13S.14@1.483,-7.821 1.483,-7.517 2.8,-6.2 C18S.1@3.1,-6.2 v1(4.325,-6.2) ; U12M.1@19.158,-4.571 C34M.1@19.158,-2.771
  Bottom Layer w0.4: C34M.1@19.208,-2.721 J16M.1@19.208,-1.271
  Bottom Layer w0.5: v1(16.625,-1.379) J16M.1@17.65,-1.379 ; v1(16.775,-0.5) 17.65,-1.375 J16M.1@17.65,-1.379 ; v1(17.675,-0.429) 17.675,-1.354 J16M.1@17.65,-1.379
  other v1: -2.3,-21.075 -8.942,8.104
P3.0V_MIC: C11S.1 C14S.1 R12S.2 U10S.5 U11S.1 U12S.5 | length 23.6
  Top Layer w0.125: v1(-0.4,-31.5) -0.4,-33.651 v1(0.8,-34.851)
  Bottom Layer w0.125: R12S.2@0.877,-35.779 v1@0.877,-34.929
  Bottom Layer w0.5: C14S.1@-7.179,-37.377 -8.325,-36.231 -8.325,-34.044 U11S.1@-7.429,-33.147 -8.379,-32.197 -8.379,-31.077 C11S.1@-7.879,-30.577 -7.279,-31.177 U10S.5@-6.229,-31.177 -5.104,-30.052 -3.254,-30.052 -2.954,-30.352 -0.454,-30.352 -0.106,-30.7 ; v1(-0.4,-31.5) -0.4,-30.994 -0.106,-30.7 ; U12S.5@0.571,-31.377 -0.106,-30.7
RF_CLK: U10M.15 U10M.54 | length 12.9
  Top Layer w0.125: v1(-3.625,8.4) -1.625,6.4 v1(-1.625,-1.2)
  Bottom Layer w0.125: v1(-3.625,8.4) -3.342,8.117 U10M.54@-3.342,7.259 ; U10M.15@-2.342,-0.501 -1.949,-0.501 -1.625,-0.825 v1(-1.625,-1.2)
RF_PKT_RDY: U10M.23 U10M.49
RF_RESET: U10M.9 U10M.48 | length 7.3
  Bottom Layer w0.125: U10M.48@-6.342,7.259 -6.342,6.779 -6.067,6.504 -5.342,6.504 -2.492,3.654 -2.492,2.904 -2.217,2.629 U10M.9@-1.712,2.629
RF_XTA: C15M.1 U10M.46 Y10M.1 | length 8.1
  Bottom Layer w0.125: U10M.46@-7.342,7.259 -7.342,8.079 -6.767,8.654 -6.142,8.654 -5.742,9.054 -5.742,10.429 Y10M.1@-6.792,11.479 -5.707,12.563 -5.707,12.7 -5.228,13.179 C15M.1@-5.192,13.179
RF_XTB: C14M.1 U10M.47 Y10M.2 | length 6
  Bottom Layer w0.125: U10M.47@-6.842,7.259 -6.842,7.954 -6.492,8.304 -5.267,8.304 -4.592,8.979 Y10M.2@-4.592,9.879 -4.292,10.179 C14M.1@-2.992,10.179
RFIO: L11M.1 U10M.39 | length 2
  Bottom Layer w0.125: L11M.1@-11.442,5.079 -11.392,5.129 U10M.39@-9.472,5.129
SCL: R10D.2 R10M.1 U10M.24 U10T.2 U11M.13 U12B.16 U13B.A3 U13S.4 | length 11.3
  Bottom Layer w0.125: R10M.1@-4.263,-13.041 -1.487,-13.041 ; U13S.4@-0.492,-9.796 -0.492,-10.746 -0.879,-11.134 -0.879,-12.434 -1.487,-13.041 ; -0.232,-14.296 -1.487,-13.041 ; 13.6,-15.4 14.93,-15.4 U13B.A3@16.208,-14.121
SDA: R11M.1 R12D.2 U10M.25 U10T.3 U11M.14 U12B.17 U13B.A2 U13S.6 | length 14
  Top Layer w0.125: v1(-2.767,-12.571) -1.067,-12.571 v1(-0.542,-13.096)
  Bottom Layer w0.125: v1(-2.767,-12.571) -3.597,-11.741 R11M.1@-4.263,-11.741 -4.263,-11.617 U13S.6@-1.467,-8.821 ; v1(-0.542,-13.096) 0.358,-13.996 ; 12.683,-15.046 14.783,-15.046 15.333,-14.496 15.333,-14.021 15.733,-13.621 U13B.A2@16.208,-13.621
SPI1_MISO: U10M.32 U10R.14
SPI1_MOSI: JP10D.19 R12D.1 R13D.2 U10M.34 U10R.13 | length 6.1
  Top Layer w0.25: JP10D.19@2.422,19.684 v1(2.422,21.834)
  Bottom Layer w0.125: R12D.1@1.472,20.184 1.472,20.884 v1(2.422,21.834) 3.072,21.184 R13D.2@3.072,20.184
SPI1_SCK: JP10D.18 R10D.1 U10M.28 U10R.11 | length 4.4
  Top Layer w0.25: JP10D.18@1.722,19.684 v1(1.722,21.834)
  Bottom Layer w0.125: v1(1.722,21.834) 1.722,23.834 R10D.1@1.872,23.984
SWD_CLK_TOUCH1: P16M.2 U10M.10 | length 3.5
  Bottom Layer w0.125: U10M.10@-1.712,2.129 0.508,2.129 0.908,1.729 1.6,1.729
SWD_DIO_TOUCH4: P16M.1 U10M.11 | length 3
  Bottom Layer w0.125: U10M.11@-1.712,1.629 0.558,1.629 0.758,1.429 1.178,1.429
TOUCH2: P15M.3 U10M.14 | length 4.9
  Bottom Layer w0.125: U10M.14@-1.712,0.129 -1.167,0.129 -0.867,-0.171 -0.867,-2.981 P15M.3@-1.682,-3.796
TOUCH3: P15M.2 U10M.13 | length 6
  Bottom Layer w0.125: U10M.13@-1.712,0.629 -0.792,0.629 -0.092,-0.071 -0.092,-2.846 P15M.2@0.858,-3.796
TOUCH5: P15M.1 U10M.12 | length 8.1
  Bottom Layer w0.125: U10M.12@-1.712,1.129 0.158,1.129 0.858,0.429 0.858,-1.256 P15M.1@3.398,-3.796
TOUCH6: P15M.4 U10M.18 | length 5.1
  Bottom Layer w0.125: P15M.4@-4.222,-3.796 -3.396,-3.796 -2.617,-3.017 -2.617,-1.871 -3.117,-1.371 -3.417,-1.371 -3.842,-0.946 U10M.18@-3.842,-0.501
TOUCH7: P15M.5 U10M.21 | length 3.9
  Bottom Layer w0.125: P15M.5@-6.762,-3.796 -6.762,-2.641 -5.342,-1.221 U10M.21@-5.342,-0.501
TOUCH8: P15M.6 U10M.22 | length 5.3
  Bottom Layer w0.125: P15M.6@-9.302,-3.796 -7.502,-1.996 -6.567,-1.996 -5.842,-1.271 U10M.22@-5.842,-0.501
TPAD0: P12M.1 U10T.19 | length 6.2
  Top Layer w0.15: P12M.1@-2.75,-30.175 v1(-2.75,-28.75)
  Bottom Layer w0.15: v1(-2.75,-28.75) -3.325,-28.175 -3.325,-26.25 -2.666,-25.591 U10T.19@-1.553,-25.591
TPAD1: P12M.2 U10T.18 | length 5.4
  Top Layer w0.15: P12M.2@-2.25,-30.175 v1(-2.25,-29.35)
  Bottom Layer w0.15: v1(-2.25,-29.35) -2.25,-28.275 -2.775,-27.75 -2.775,-26.375 -2.391,-25.991 U10T.18@-1.553,-25.991
TPAD2: P12M.3 U10T.17 | length 4.7
  Top Layer w0.15: P12M.3@-1.75,-30.175 v1(-1.75,-28.75)
  Bottom Layer w0.15: v1(-1.75,-28.75) -1.75,-28.075 -2.325,-27.5 -2.325,-26.625 -2.091,-26.391 U10T.17@-1.553,-26.391
TPAD3: P12M.4 U10T.16 | length 3.5
  Top Layer w0.15: P12M.4@-1.25,-30.175 v1(-1.25,-29.35)
  Bottom Layer w0.15: U10T.16@-1.553,-26.791 -1.553,-27.572 -1.25,-27.875 v1(-1.25,-29.35)
TPAD4: P12M.5 U10T.15 | length 2.6
  Top Layer w0.15: P12M.5@-0.75,-30.175 v1(-0.75,-28.75)
  Bottom Layer w0.15: U10T.15@-0.778,-27.566 -0.778,-28.722 v1(-0.75,-28.75)
TPAD5: P12M.6 U10T.14 | length 2.7
  Top Layer w0.15: P12M.6@-0.25,-30.175 v1(-0.25,-29.35)
  Bottom Layer w0.15: U10T.14@-0.378,-27.566 -0.378,-28.247 -0.25,-28.375 v1(-0.25,-29.35)
TPAD6: P12M.7 U10T.13 | length 2.7
  Top Layer w0.15: P12M.7@0.25,-30.175 v1(0.25,-28.75)
  Bottom Layer w0.15: U10T.13@0.022,-27.566 0.022,-28.222 0.25,-28.45 v1(0.25,-28.75)
TPAD7: P12M.8 U10T.12 | length 2.7
  Top Layer w0.15: P12M.8@0.75,-30.175 v1(0.75,-29.35)
  Bottom Layer w0.15: U10T.12@0.422,-27.566 0.422,-28.147 0.75,-28.475 v1(0.75,-29.35)
TPAD8: P12M.9 U10T.11 | length 2.8
  Top Layer w0.15: P12M.9@1.25,-30.175 v1(1.25,-28.75)
  Bottom Layer w0.15: U10T.11@0.822,-27.566 0.822,-27.972 1.25,-28.4 v1(1.25,-28.75)
TPADA: P12M.12 U10T.8 | length 5.1
  Top Layer w0.15: P12M.12@2.75,-30.175 v1(2.75,-29.35)
  Bottom Layer w0.15: U10T.8@1.597,-25.991 2.316,-25.991 2.775,-26.45 2.775,-29.325 v1(2.75,-29.35)
TPADB: P12M.11 U10T.9 | length 4.4
  Top Layer w0.15: P12M.11@2.25,-30.175 v1(2.25,-28.75)
  Bottom Layer w0.15: U10T.9@1.597,-26.391 2.141,-26.391 2.325,-26.575 2.325,-27.9 2.25,-27.975 v1(2.25,-28.75)
TPADC: P12M.10 U10T.10 | length 3.4
  Top Layer w0.15: P12M.10@1.75,-30.175 v1(1.75,-29.35)
  Bottom Layer w0.15: U10T.10@1.597,-26.791 1.597,-28.197 1.75,-28.35 v1(1.75,-29.35)
USBD_N: D12B.1 P11B.2 U12B.15 | length 5.3
  Bottom Layer w0.125: D12B.1@-18.473,-9.379 -17.998,-8.904 -16.073,-8.904
  Bottom Layer w0.2: P11B.2@-20.989,-9.844 -18.938,-9.844 D12B.1@-18.473,-9.379
USBD_P: D13B.1 P11B.3 U12B.14 | length 5.5
  Bottom Layer w0.125: D13B.1@-18.473,-8.179 -17.998,-8.654 -16.073,-8.654
  Bottom Layer w0.2: P11B.3@-20.916,-9.198 -19.492,-9.198 D13B.1@-18.473,-8.179
USBOUT_EN_N: U11M.6
VBAT_SYS: C15B.1 C16B.1 C17B.1 C18B.1 C19B.1 C25B.1 L10B.2 R21B.2 R25B.2 R26B.2 U12B.6 U12B.7 U13B.C3 | length 30.3
  Bottom Layer w0.2: 12.172,-28.391 12.347,-28.216 ; 12.172,-27.666 U12B.7@12.372,-27.466 ; U13B.C3@17.208,-14.121 17.508,-14.421 ; R21B.2@19.208,-16.971 21.458,-16.971 R26B.2@21.508,-17.021
  Bottom Layer w0.3: v1(11.525,-28) 12.172,-28 ; 12.172,-28.391 12.172,-28 ; 12.172,-27.666 12.172,-28 ; 12.347,-28.216 U12B.6@13.122,-28.216
  Bottom Layer w0.4: 17.508,-14.421 C25B.1@17.508,-15.721 17.958,-15.721 R21B.2@19.208,-16.971
  Bottom Layer w0.5: v1(10.875,-29.85) 10.909,-29.816 C16B.1@12.172,-29.816 v1@12.172,-28.7 ; v1(10.95,-28.7) v1@12.172,-28.7 ; 12.172,-28.391 v1@12.172,-28.7 ; v1(16.5,-20.3) R25B.2@15.35,-20.3 v1(17.15,-18.5) 19,-18.5 ; R21B.2@19.208,-16.971 19.208,-18.292 19,-18.5 ; L10B.2@21.872,-26.516 21.372,-26.016 C15B.1@21.372,-24.716 C18B.1@21.372,-22.916 C19B.1@21.372,-21.416 C17B.1@21.372,-19.916 21.372,-19.066 20.806,-18.5 19,-18.5
  other v1: 12,-28.7 16.55,-19.1 18.025,-18.5
VR_PA: C19M.1 C20M.1 L10M.1 U10M.42 | length 4.9
  Bottom Layer w0.3: L10M.1@-13.792,8.129 -11.092,8.129 -9.592,6.629 U10M.42@-9.472,6.629
VSYS: C10S.1 C12D.1 C33M.1 J10D.1 J15M.1 JP10D.6 R21B.1 U10S.1 U10S.3 U12M.2 U12M.7 U13B.C2 | length 40.5
  Top Layer w0.25: v1(-6.678,17.534) JP10D.6@-6.678,19.684
  Bottom Layer w0.2: C10S.1@-6.379,-27.177 -6.379,-26.804 -5.925,-26.35 -4.65,-26.35 -4.329,-26.671 U10S.3@-4.329,-28.777 ; U12M.7@16.858,-5.071 15.029,-5.071 14.6,-5.5 14.6,-7.8 15,-8.2 18.9,-8.2 19.7,-9 ; U13B.C2@17.208,-13.621 17.608,-13.621
  Bottom Layer w0.4: v1(-7.104,-26.652) -6.579,-27.177 C10S.1@-6.379,-27.177 -6.229,-27.327 U10S.1@-6.229,-28.777 ; v1(-6.678,17.534) -6.678,19.434 C12D.1@-6.428,19.684 -6.428,22.934 J10D.1@-6.228,23.134 ; 17.608,-13.621 R21B.1@18.758,-13.621 ; U12M.2@19.158,-5.071 20.558,-5.071 C33M.1@20.908,-4.721
  Bottom Layer w0.7: C33M.1@20.908,-4.721 21.921,-4.721 22.25,-5.05 J15M.1@22.25,-8.2
  Bottom Layer w1: R21B.1@19.208,-14.071 19.7,-13.58 19.7,-9 20.5,-8.2 J15M.1@20.75,-8.2
  other v1: 19.5,-12.65 19.525,-11.575 19.5,-9.85
VUSB: C10L.1 C11B.1 C12L.1 C13L.1 C20B.1 C24B.1 D10M.2 D11B.1 J10L.1 P10L.3 P11B.1 U10B.1 U10B.4 U12B.18 U12B.19 U16L.1 U18L.1 U19L.1 | length 39.9
  Top Layer w0.5: U18L.1@-19.15,24.15 -19.075,24.225 v1(-19.075,25.725) ; U19L.1@15.85,24.15 16.3,24.6 v1(16.3,25.875)
  Bottom Layer w0.2: U16L.1@9.816,32.422 11.266,32.422 C10L.1@11.616,32.772 v1(11.616,33.897) ; 16.197,-24.216 v1@16.372,-24.041
  Bottom Layer w0.3: U10B.1@5.828,-26.528 5.828,-27.028 U10B.4@7.728,-28.928 ; U12B.18@15.622,-24.216 16.197,-24.216 ; U12B.19@16.372,-24.966 v1@16.372,-24.041
  Bottom Layer w0.5: P11B.1@-20.882,-10.5 -19.051,-10.5 D11B.1@-18.623,-10.929 ; v1(-19.075,25.725) -17.575,25.725 C12L.1@-17.3,26 ; -18.748,-10.754 D11B.1@-18.623,-10.929 ; C24B.1@-17.223,-10.879 -17.273,-10.929 D11B.1@-18.623,-10.929 ; v1(-0.3,32.4) J10L.1@0.85,32.4 ; v1(0.85,31.425) J10L.1@0.85,32.4 ; v1(0.85,33.4) J10L.1@0.85,32.4 ; J10L.1@2.35,32.4 2.472,32.522 P10L.3@2.472,35.684 ; P10L.3@2.472,35.459 P10L.3@2.472,35.684 ; P10L.3@2.922,35.234 P10L.3@2.472,35.684 ; D10M.2@15.9,23.9 16.525,23.9 17.6,24.975 C13L.1@17.6,25.9 16.325,25.9 v1(16.3,25.875) ; v1@16.372,-24.041 v1(16.472,-23.941) v1(16.997,-23.416) ; v1@16.372,-22.841 16.422,-22.841 v1(16.997,-23.416) ; C20B.1@18.272,-23.116 17.297,-23.116 v1(16.997,-23.416) ; P10L.3@2.472,35.684 P10L.3@2.472,36.284 P10L.3@2.472,35.684
  Bottom Layer w0.8: C24B.1@-17.223,-10.879 v1(-15.473,-10.879) -15.173,-11.179 v1(-15.173,-11.854) ; U10B.4@7.728,-28.928 8.178,-29.378 C11B.1@8.178,-30.628 ; v1@8.171,-32.153 8.171,-30.845 8.065,-30.739 C11B.1@8.206,-30.739
  other v1: 8.153,-32.277 8.171,-31.623 16.397,-22.841 -16.248,-10.904 17.35,24.7
pads on no net: JP10D.0 JP10D.7 P11B.4 P11M.2 P11M.6 P12M.0 U10M.30 U10M.37 U10M.41 U10M.50 U10M.51 U10M.52 U10M.53 U10M.57 U10M.58 U10M.59 U10M.60 U10R.4 U10R.5 U10R.6 U10R.15 U10S.4 U12B.11 U12M.5 U13S.3 U13S.8 U13S.9 U13S.13 U13S.15 U13S.16

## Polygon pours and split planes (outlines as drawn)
GND on Top Layer "gnd-top" (solid, remove dead copper, shelved, pour order 2): 5.997,-48.341 63.047,-48.341 63.072,-48.316 63.072,-13.441 5.947,-13.441 5.872,-13.516
GND on Bottom Layer "gnd-bot" (solid, remove dead copper, shelved, pour order 4): 6.072,-13.316 6.072,-48.316 63.072,-48.316 63.072,-13.316 6.172,-13.316 5.997,-13.491
VBAT_SYS on Internal Plane 1 (split plane): 18.873,-17.892 18.873,-19.158 15.703,-22.328 15.681,-22.361 15.673,-22.4 15.673,-24.3 15.681,-24.339 15.703,-24.372 16.448,-25.117 16.448,-27.158 15.333,-28.273 13.725,-28.273 13.686,-28.281 13.653,-28.303 11.383,-30.573 9.492,-30.573 8.594,-29.675 13.772,-24.497 13.794,-24.464 13.802,-24.425 13.802,-20.717 17.75,-16.769
VSYS on Internal Plane 1 (split plane): 15.528,22.328 15.561,22.306 15.6,22.298 17.958,22.298 19.498,20.758 19.498,-1.4 19.506,-1.439 19.528,-1.472 20.398,-2.342 20.398,-8.558 19.928,-9.028 19.906,-9.061 19.898,-9.1 19.898,-14.333 13.628,-20.603 13.606,-20.636 13.598,-20.675 13.598,-24.383 7.933,-30.048 5.525,-30.048 5.486,-30.056 5.453,-30.078 2.708,-32.823 -2.958,-32.823 -3.953,-31.828 -3.986,-31.806 -4.025,-31.798 -6.898,-31.798 -6.898,-27.8 -6.906,-27.761 -6.928,-27.728 -7.798,-26.858 -7.798,-26.542 -7.358,-26.102 -6.442,-26.102 -4.472,-28.072 -4.439,-28.094 -4.4,-28.102 -3.867,-28.102 -3.602,-28.367 -3.602,-29.775 -3.594,-29.814 -3.572,-29.847 -2.447,-30.972 -2.414,-30.994 -2.375,-31.002 2.6,-31.002 2.639,-30.994 2.672,-30.972 4.672,-28.972 11.697,-21.947 11.719,-21.914 11.727,-21.875 11.727,-19.598 18.772,-12.553 18.794,-12.52 18.802,-12.481 18.802,-7.596 19.608,-7.596 19.608,-3.296 18.802,-3.296 18.802,-2.9 18.794,-2.861 18.772,-2.828 18.302,-2.358 18.302,20.1 18.294,20.139 18.272,20.172 17.472,20.972 17.439,20.994 17.4,21.002 12.9,21.002 12.861,20.994 12.828,20.972 10.858,19.002 -4.2,19.002 -4.239,18.994 -4.272,18.972 -6.442,16.802 -7.158,16.802 -7.398,17.042 -7.398,18.558 -5.758,20.198 10.9,20.198 10.939,20.206 10.972,20.228 14.3,23.556
P3.0V on Internal Plane 1 (split plane): 10.028,30.728 10.061,30.706 10.1,30.698 11.758,30.698 13.398,29.058 13.398,24.5 13.406,24.461 13.428,24.428 14.156,23.7 10.858,20.402 -5.8,20.402 -5.839,20.394 -5.872,20.372 -7.572,18.672 -7.594,18.639 -7.602,18.6 -7.602,17 -7.594,16.961 -7.572,16.928 -7.272,16.628 -7.239,16.606 -7.2,16.598 -6.4,16.598 -6.361,16.606 -6.328,16.628 -4.158,18.798 10.9,18.798 10.939,18.806 10.972,18.828 12.942,20.798 17.358,20.798 18.098,20.058 18.098,-2.4 18.106,-2.439 18.128,-2.472 18.598,-2.942 18.598,-12.439 11.553,-19.484 11.531,-19.517 11.523,-19.556 11.523,-21.833 4.528,-28.828 2.558,-30.798 -2.333,-30.798 -3.398,-29.733 -3.398,-28.325 -3.406,-28.286 -3.428,-28.253 -3.753,-27.928 -3.786,-27.906 -3.825,-27.898 -4.358,-27.898 -6.328,-25.928 -6.361,-25.906 -6.4,-25.898 -7.4,-25.898 -7.439,-25.906 -7.472,-25.928 -7.972,-26.428 -7.994,-26.461 -8.002,-26.5 -8.002,-26.9 -7.994,-26.939 -7.972,-26.972 -7.102,-27.842 -7.102,-31.798 -17.558,-31.798 -19.898,-29.458 -19.898,-27.842 -19.428,-27.372 -19.406,-27.339 -19.398,-27.3 -19.398,-16.542 -17.058,-14.202 -15.4,-14.202 -15.361,-14.194 -15.328,-14.172 -13.628,-12.472 -13.606,-12.439 -13.598,-12.4 -13.598,-11.2 -13.606,-11.161 -13.628,-11.128 -14.828,-9.928 -14.861,-9.906 -14.9,-9.898 -25.09,-9.898 -25.09,6.589 -23.346,8.332 -23.283,8.409 -23.236,8.498 -23.206,8.593 -23.197,8.693 -23.197,22.498 -15,22.498 -14.961,22.506 -14.928,22.528 -14.128,23.328 -14.106,23.361 -14.098,23.4 -14.098,29.658 -13.058,30.698 1.8,30.698 1.839,30.706 1.872,30.728 4.342,33.198 7.558,33.198
VUSB on Internal Plane 1 (split plane): 203 vertices, not listed, extent -25.09,-38.192 23.198,38.206
GND on Internal Plane 2 (split plane): 20.442,38.197 20.675,38.169 20.906,38.123 21.132,38.06 21.352,37.978 21.565,37.88 21.77,37.765 21.966,37.635 22.15,37.489 22.323,37.33 22.482,37.157 22.628,36.973 22.758,36.778 22.873,36.573 22.971,36.359 23.053,36.139 23.116,35.913 23.162,35.682 23.19,35.449 23.198,35.23 23.197,35.214 23.197,-35.186 23.197,-35.187 23.197,-35.201 23.198,-35.217 23.19,-35.435 23.162,-35.668 23.116,-35.898 23.053,-36.125 22.971,-36.345 22.873,-36.558 22.758,-36.763 22.628,-36.959 22.482,-37.143 22.323,-37.316 22.15,-37.475 21.966,-37.621 21.77,-37.751 21.565,-37.866 21.352,-37.964 21.132,-38.046 20.906,-38.109 20.675,-38.155 20.442,-38.183 20.214,-38.192 20.194,-38.19 -20.207,-38.19 -20.223,-38.191 -20.442,-38.183 -20.675,-38.155 -20.906,-38.109 -21.132,-38.045 -21.352,-37.964 -21.565,-37.866 -21.77,-37.751 -21.966,-37.621 -22.15,-37.475 -22.323,-37.316 -22.482,-37.143 -22.628,-36.959 -22.758,-36.763 -22.873,-36.558 -22.971,-36.345 -23.053,-36.125 -23.116,-35.898 -23.162,-35.668 -23.19,-35.435 -23.198,-35.217 -23.197,-35.2 -23.197,-20.31 -23.206,-20.21 -23.236,-20.115 -23.283,-20.026 -23.346,-19.949 -25.09,-18.206 -25.09,6.589 -23.346,8.332 -23.283,8.409 -23.236,8.498 -23.206,8.593 -23.197,8.693 -23.197,35.2 -23.199,35.22 -23.19,35.449 -23.162,35.682 -23.116,35.913 -23.052,36.139 -22.971,36.359 -22.873,36.572 -22.758,36.777 -22.628,36.973 -22.482,37.157 -22.323,37.33 -22.15,37.489 -21.966,37.635 -21.77,37.765 -21.565,37.88 -21.352,37.978 -21.132,38.06 -20.906,38.123 -20.675,38.169 -20.442,38.197 -20.223,38.205 -20.207,38.204 20.179,38.204 20.199,38.206 20.207,38.206

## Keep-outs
Keep-Out Layer:
  lines w0.2: -23.707,8.693 -23.707,22.3
  lines w0.5: -25.6,-18.417 -25.6,6.8 -23.707,8.693
  lines w1: -25.6,-18.417 -23.707,-20.31 -23.707,-35.2 ccw(c-20.207,-35.2) -20.207,-38.7 20.194,-38.7 ccw(c20.207,-35.2) 23.707,-35.2 ; -23.707,22.3 -23.707,35.2 cw(c-20.207,35.214) -20.207,38.714 20.179,38.714 cw(c20.207,35.214) 23.707,35.214 23.707,-35.186

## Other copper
Bottom Layer:
  pour cut-out: -15.507,36 -15.507,37.7 -10.407,37.7 -10.407,36
  text "4" at -11.307,36.7 h0.7
Internal Plane 1 (plane layer: these items are gaps in the copper):
  rectangle: -15.507,36.3 -14.707,37.7
  rectangle: -13.807,36.3 -10.407,37.7
  region: 19.608,-7.596 19.608,-3.296 18.658,-3.296 18.658,-7.596
  lines w0.2: -25.7,-10 -19.9,-10 ; -23.607,22.6 -15,22.6 -14.2,23.4 -14.2,29.7 -13.1,30.8 1.8,30.8 4.3,33.3 7.6,33.3 10.1,30.8 11.8,30.8 13.5,29.1 13.5,24.5 15.6,22.4 18,22.4 19.6,20.8 19.6,-1.4 20.5,-2.3 20.5,-8.6 20,-9.1 20,-14.375 13.7,-20.675 13.7,-24.425 7.975,-30.15 5.525,-30.15 2.75,-32.925 -3,-32.925 -4.025,-31.9 -17.6,-31.9 -20,-29.5 -20,-27.8 -19.5,-27.3 -19.5,-16.5 -17.1,-14.1 -15.4,-14.1 -13.7,-12.4 -13.7,-11.2 -14.9,-10 -20,-10 ; -7,-31.9 -7,-27.8 -7.9,-26.9 -7.9,-26.5 -7.4,-26 -6.6,-26 -6.4,-26 -4.4,-28 -3.825,-28 -3.5,-28.325 -3.5,-29.775 -2.375,-30.9 2.6,-30.9 4.6,-28.9 11.625,-21.875 11.625,-19.556 18.7,-12.481 18.7,-2.9 18.2,-2.4 18.2,20.1 17.4,20.9 12.9,20.9 10.9,18.9 -4.2,18.9 -6.4,16.7 -7.2,16.7 -7.5,17 -7.5,18.6 -5.8,20.3 10.9,20.3 14.3,23.7 ; 8.475,-29.7 9.45,-30.675 11.425,-30.675 13.725,-28.375 15.375,-28.375 16.55,-27.2 16.55,-25.075 15.775,-24.3 15.775,-22.4 18.975,-19.2 18.975,-17.85 17.775,-16.65
  text "2" at -14.507,36.7 h0.7
Internal Plane 2 (plane layer: these items are gaps in the copper):
  rectangle: -15.507,36.1 -12.307,37.7
  rectangle: -11.507,36 -10.407,37.7
  text "3" at -12.107,36.7 h0.7

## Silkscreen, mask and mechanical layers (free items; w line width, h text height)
Bottom Overlay:
  circle w0.127: c45.605,-5.041 r0.583
  lines w0.2: 40.707,-14.67 ccw(c41.723,-14.67) 41.723,-15.686 48.983,-15.686 ccw(c48.983,-14.819) 49.851,-14.819 49.851,-10.098 ccw(c48.835,-10.098) 48.835,-9.082 41.723,-9.082 ccw(c41.723,-10.098) 40.707,-10.098 40.707,-14.67
  text "c bunnie@kosagi.com" at 45.872,-5.291 h0.76
  text "CERN OHL v1.2" at 46.172,-6.791 h0.76
  text "Designed in" at 39.669,-12.356 h0.76
  text "Singapore" at 39.669,-13.756 h0.76
  text "02/15" at 39.622,-15.216 h0.76
Top Solder:
  region: -10.407,36 -10.407,37.7 -15.507,37.7 -15.507,36
Bottom Solder:
  region: -10.407,36 -10.407,37.7 -15.507,37.7 -15.507,36
Mechanical 3:
  lines w0.127: 69.449,-41.957 70.719,-43.227 ; 69.449,12.653 70.719,13.923 ; 71.989,-41.957 70.719,-43.227 ; 71.989,12.653 70.719,13.923 ; 94.849,-39.417 136.759,-39.417 ; 94.849,-26.177 136.759,-26.177 134.219,-28.717 ; 94.849,-0.587 136.759,-0.587 134.219,-3.127 ; 94.849,10.113 136.759,10.113 ; 96.119,-28.717 98.659,-26.177 ; 96.119,-3.127 98.659,-0.587 ; 97.389,-38.147 98.659,-39.417 ; 97.389,-28.717 99.929,-26.177 ; 97.389,-26.177 94.849,-28.717 136.759,-28.717 ; 97.389,-3.127 99.929,-0.587 ; 97.389,-0.587 94.849,-3.127 136.759,-3.127 ; 97.389,8.843 98.659,10.113 ; 98.659,-28.717 101.199,-26.177 ; 98.659,-3.127 101.199,-0.587 ; 99.929,-38.147 98.659,-39.417 ; 99.929,8.843 98.659,10.113 ; 101.199,-28.717 103.739,-26.177 ; 101.199,-3.127 103.739,-0.587 ; 102.469,-28.717 105.009,-26.177 ; 102.469,-3.127 105.009,-0.587 ; 103.739,-28.717 106.279,-26.177 ; 103.739,-3.127 106.279,-0.587 ; 106.279,-28.717 108.819,-26.177 ; 106.279,-3.127 108.819,-0.587 ; 107.549,-28.717 110.089,-26.177 ; 107.549,-3.127 110.089,-0.587 ; 108.819,-28.717 111.359,-26.177 ; 108.819,-3.127 111.359,-0.587 ; 110.089,-28.717 112.629,-26.177 ; 110.089,-3.127 112.629,-0.587 ; 112.629,-28.717 115.169,-26.177 ; 112.629,-3.127 115.169,-0.587 ; 113.899,-28.717 116.439,-26.177 ; 113.899,-3.127 116.439,-0.587 ; 115.169,-28.717 117.709,-26.177 ; 115.169,-3.127 117.709,-0.587 ; 116.439,-28.717 118.979,-26.177 ; 116.439,-3.127 118.979,-0.587 ; 118.979,-28.717 121.519,-26.177 ; 118.979,-3.127 121.519,-0.587 ; 120.249,-28.717 122.789,-26.177 ; 120.249,-3.127 122.789,-0.587 ; 124.059,-28.717 126.599,-26.177 ; 124.059,-3.127 126.599,-0.587 ; 125.329,-28.717 127.869,-26.177 ; 125.329,-3.127 127.869,-0.587 ; 127.851,11.436 129.121,12.706 ; 127.876,-40.809 129.146,-39.539 ; 127.876,-39.539 127.876,-42.079 ; 129.121,10.166 131.661,12.706 ; 129.139,-28.717 131.679,-26.177 ; 129.139,-3.127 131.679,-0.587 ; 129.146,-42.079 131.686,-39.539 131.686,-42.079 127.876,-42.079 ; 130.391,12.706 127.851,10.166 127.851,12.706 131.661,12.706 ; 130.409,-28.717 132.949,-26.177 ; 130.409,-3.127 132.949,-0.587 ; 130.416,-42.079 131.686,-40.809 ; 131.661,10.166 131.661,12.706 ; 131.661,11.436 130.391,10.166 131.661,8.896 138.011,8.896 ; 131.679,-28.717 134.219,-26.177 ; 131.679,-3.127 134.219,-0.587 ; 132.949,-28.717 135.489,-26.177 ; 132.949,-3.127 135.489,-0.587 ; 135.489,-28.717 136.759,-27.447 ; 135.489,-3.127 136.759,-1.857 ; 138.036,-38.269 131.686,-38.269 130.416,-39.539 127.876,-42.079 ; 70.719,-43.227 70.719,13.923 ; 98.659,-39.417 98.659,10.113 ; 94.849,-27.447 96.119,-26.177 94.849,-27.447 ; 94.849,-1.857 96.119,-0.587 94.849,-1.857 ; 99.929,-28.717 102.469,-26.177 99.929,-28.717 ; 99.929,-3.127 102.469,-0.587 99.929,-3.127 ; 105.009,-28.717 107.549,-26.177 105.009,-28.717 ; 105.009,-3.127 107.549,-0.587 105.009,-3.127 ; 111.359,-28.717 113.899,-26.177 111.359,-28.717 ; 111.359,-3.127 113.899,-0.587 111.359,-3.127 ; 117.709,-28.717 120.249,-26.177 117.709,-28.717 ; 117.709,-3.127 120.249,-0.587 117.709,-3.127 ; 121.519,-28.717 124.059,-26.177 121.519,-28.717 ; 121.519,-3.127 124.059,-0.587 121.519,-3.127 ; 122.789,-28.717 125.329,-26.177 122.789,-28.717 ; 122.789,-3.127 125.329,-0.587 122.789,-3.127 ; 126.599,-28.717 129.139,-26.177 126.599,-28.717 ; 126.599,-3.127 129.139,-0.587 126.599,-3.127 ; 127.869,-28.717 130.409,-26.177 127.869,-28.717 ; 127.869,-3.127 130.409,-0.587 127.869,-3.127
  text "Board name: Orchard Bootcamp EVT1" at 83.119,27.953 h1
  text "Contact: bunnie@kosagi.com" at 83.119,25.413 h1
  text "Silk: white" at 108.86,18.006 h0.76
  text "Soldermask: matte black" at 108.735,16.506 h0.76
  text "Material and thickness" at 68.179,16.463 h1.27
  text "Impedance control" at 139.754,16.413 h1.27
  text "Finish: Immersion gold" at 108.735,15.156 h0.76
  text "Plate 0.5 oz" at 83.419,11.383 h0.76
  text "Top-bottom pair" at 98.659,11.383 h0.76 r45
  text "Copper 0.5 oz" at 83.419,10.113 h0.76
  text "0.125mm = 50 ohm +/- 10%" at 139.281,8.896 h0.76
  text "Total 1.0 oz" at 83.419,8.589 h0.76
  text "Core" at 73.259,1.953 h0.76
  text "FR-4 0.125mm" at 83.419,1.953 h0.76
  text "Copper 1 oz" at 83.419,-1.857 h0.76
  text "Plane" at 140.569,-1.857 h0.76
  text "0.035mm" at 86.467,-3.127 h0.76
  text "Core" at 73.259,-15.287 h0.76
  text "FR-4 height as needed to meet overall height spec" at 83.419,-15.287 h0.76
  text "Overall height: 1.0mm +/-10%" at 69.449,-20.367 h0.76 r90
  text "Copper 1 oz" at 83.419,-27.447 h0.76
  text "0.035mm" at 86.467,-28.717 h0.76
  text "Plane" at 140.569,-28.717 h0.76
  text "Core" at 73.259,-32.527 h0.76
  text "FR-4 0.125mm" at 83.419,-32.527 h0.76
  text "Diff pairs also mirror top side impedance traits" at 139.085,-36.217 h0.76
  text "0.125mm = 50 ohm +/- 10%" at 139.052,-38.269 h0.76
  text "Copper 0.5 oz" at 83.419,-40.687 h0.76
  text "Finish: Immersion gold" at 108.81,-41.594 h0.76
  text "Plate 0.5 oz" at 83.419,-41.957 h0.76
  text "Soldermask: matte black" at 108.685,-43.194 h0.76
  text "Total 1.0oz" at 83.578,-43.525 h0.76
  text "Silk: white" at 108.81,-44.794 h0.76
  text "Mech via: 0.25mm hole / 0.5mm pad smallest" at 83.269,-46.907 h0.76
  text "Route: 0.125mm / 0.125mm smallest" at 83.269,-49.447 h0.76
Mechanical 4:
  drawing of 228 lines, arcs and shapes, not listed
